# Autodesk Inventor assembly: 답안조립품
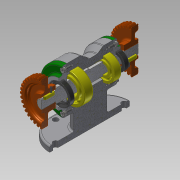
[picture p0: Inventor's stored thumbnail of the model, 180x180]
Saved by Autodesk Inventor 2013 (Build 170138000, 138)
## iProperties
Created: 2020-01
Part Number: 답안조립품
Document SubType Name: Assembly
Designer: Administrator
Author: Administrator
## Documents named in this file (13)
- C:\Users\Administrator\Desktop\700104V1010\답안조립품.iam
- C:\Users\Administrator\Desktop\700104V1010\본체.ipt
- C:\Users\Administrator\Desktop\700104V1010\뒤커버.ipt
- C:\Users\Administrator\Desktop\700104V1010\멈춤나사 M3.ipt
- C:\Users\Administrator\Desktop\700104V1010\베어링 6203.ipt
- C:\Users\Administrator\Desktop\700104V1010\베어링 6205.ipt
- C:\Users\Administrator\Desktop\700104V1010\볼트 M4.ipt
- C:\Users\Administrator\Desktop\700104V1010\스퍼기어.ipt
- C:\Users\Administrator\Desktop\700104V1010\앞커버.ipt
- C:\Users\Administrator\Desktop\700104V1010\오일 실 17 30 8.ipt
- C:\Users\Administrator\Desktop\700104V1010\오일 실 25 38 8.ipt
- C:\Users\Administrator\Desktop\700104V1010\축.ipt
- C:\Users\Administrator\Desktop\700104V1010\키 5 x 5 x 18.ipt
